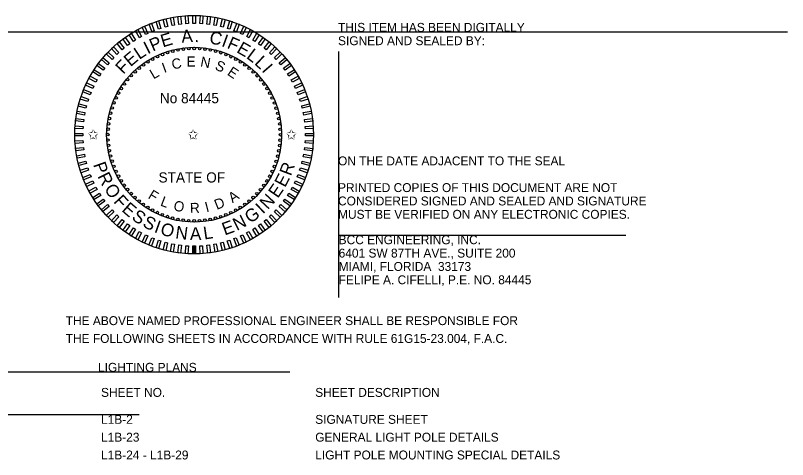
# Model space of a CAD drawing. Extents: x -811.2 to -795, y -2295.2 to -2235.1.
# Drawn here: x -802.94 to -796.87, y -2238.99 to -2235.5 of the extents above; entities that cross this region are included whole.
import ezdxf

# ---------------------------------------------------------------- set-up
doc = ezdxf.new("R2010")
doc.units = 0
for name, color, linetype in [('AdhocPoint_dp', 7, 'Continuous'), ('PlotBorder_dp', 7, 'Continuous'), ('TextMinor', 7, 'Continuous'), ('TextMisc', 7, 'Continuous'), ('TextShtNo', 7, 'Continuous')]:
    doc.layers.add(name, color=color, linetype=linetype)

msp = doc.modelspace()

# ---------------------------------------------------------------- linework, layer by layer
at = {"layer": 'AdhocPoint_dp'}
for p, q in [((-808.3596, -2235.6292), (-796.8708, -2235.6292)), ((-800.3974, -2235.7843), (-800.3974, -2237.719)), ((-800.3974, -2237.229), (-798.1407, -2237.229)), ((-809.3854, -2238.3022), (-800.7818, -2238.3022)), ((-801.9648, -2238.6414), (-810.4432, -2238.6414))]:
    msp.add_line(p, q, dxfattribs=at)
at = {"layer": 'TextMinor'}
for radius in [0.9375, 0.6875]:
    msp.add_circle((-801.5329, -2236.4379), radius, dxfattribs=at)
at = {"layer": 'TextShtNo'}
for p, q in [((-801.5429, -2237.3754), (-801.5431, -2237.3129)), ((-801.5329, -2237.3754), (-801.5331, -2237.3129)), ((-801.5229, -2237.3754), (-801.5231, -2237.3129))]:
    msp.add_line(p, q, dxfattribs=at)
for points in [[(-801.6869, -2235.5764), (-801.7067, -2235.5802), (-801.7184, -2235.5189), (-801.6986, -2235.5151)], [(-801.6325, -2235.5685), (-801.6525, -2235.571), (-801.6603, -2235.5091), (-801.6403, -2235.5065)], [(-801.5777, -2235.5639), (-801.5978, -2235.5652), (-801.6018, -2235.5029), (-801.5816, -2235.5016)], [(-801.5227, -2235.5629), (-801.5429, -2235.5629), (-801.5429, -2235.5004), (-801.5227, -2235.5004)], [(-801.4678, -2235.5652), (-801.488, -2235.564), (-801.484, -2235.5016), (-801.4639, -2235.5029)], [(-801.4131, -2235.571), (-801.4332, -2235.5685), (-801.4254, -2235.5066), (-801.4053, -2235.5091)], [(-801.359, -2235.5803), (-801.3788, -2235.5765), (-801.3671, -2235.5152), (-801.3473, -2235.5189)], [(-801.8456, -2235.6206), (-801.8643, -2235.628), (-801.8873, -2235.5699), (-801.8686, -2235.5625)], [(-801.7936, -2235.6025), (-801.8128, -2235.6088), (-801.8321, -2235.5494), (-801.8129, -2235.5432)], [(-801.7407, -2235.5878), (-801.7602, -2235.5928), (-801.7758, -2235.5324), (-801.7562, -2235.5273)], [(-801.3054, -2235.5929), (-801.325, -2235.5879), (-801.3095, -2235.5274), (-801.2899, -2235.5324)], [(-801.2528, -2235.6088), (-801.272, -2235.6026), (-801.2527, -2235.5432), (-801.2335, -2235.5494)], [(-801.2013, -2235.6281), (-801.2201, -2235.6206), (-801.1971, -2235.5626), (-801.1783, -2235.57)], [(-801.9455, -2235.6662), (-801.9632, -2235.6759), (-801.9933, -2235.6212), (-801.9756, -2235.6115)], [(-801.8963, -2235.6418), (-801.9145, -2235.6504), (-801.9411, -2235.5939), (-801.9229, -2235.5853)], [(-801.1511, -2235.6505), (-801.1694, -2235.6419), (-801.1428, -2235.5854), (-801.1246, -2235.594)], [(-801.1025, -2235.676), (-801.1201, -2235.6663), (-801.0901, -2235.6116), (-801.0724, -2235.6213)], [(-802.039, -2235.724), (-802.0553, -2235.7359), (-802.092, -2235.6853), (-802.0757, -2235.6735)], [(-801.9932, -2235.6936), (-802.0102, -2235.7044), (-802.0437, -2235.6517), (-802.0266, -2235.6409)], [(-801.0555, -2235.7045), (-801.0725, -2235.6937), (-801.039, -2235.641), (-801.022, -2235.6518)], [(-801.0104, -2235.736), (-801.0267, -2235.7241), (-800.99, -2235.6736), (-800.9737, -2235.6854)], [(-802.1245, -2235.793), (-802.1392, -2235.8069), (-802.182, -2235.7613), (-802.1672, -2235.7475)], [(-802.0828, -2235.7572), (-802.0984, -2235.77), (-802.1382, -2235.7219), (-802.1226, -2235.7091)], [(-800.9673, -2235.7702), (-800.9829, -2235.7573), (-800.9431, -2235.7092), (-800.9275, -2235.722)], [(-800.9265, -2235.807), (-800.9412, -2235.7932), (-800.8985, -2235.7477), (-800.8838, -2235.7615)], [(-802.1638, -2235.8315), (-802.1776, -2235.8462), (-802.2232, -2235.8034), (-802.2093, -2235.7887)], [(-800.8881, -2235.8463), (-800.9019, -2235.8316), (-800.8564, -2235.7889), (-800.8426, -2235.8036)], [(-802.2349, -2235.9153), (-802.2467, -2235.9316), (-802.2972, -2235.8949), (-802.2854, -2235.8786)], [(-802.2007, -2235.8723), (-802.2135, -2235.8878), (-802.2616, -2235.848), (-802.2488, -2235.8325)], [(-800.8522, -2235.888), (-800.8651, -2235.8724), (-800.817, -2235.8326), (-800.8041, -2235.8482)], [(-800.819, -2235.9318), (-800.8309, -2235.9155), (-800.7804, -2235.8788), (-800.7685, -2235.8951)], [(-802.2663, -2235.9604), (-802.2771, -2235.9775), (-802.3298, -2235.944), (-802.319, -2235.927)], [(-800.7887, -2235.9776), (-800.7995, -2235.9606), (-800.7468, -2235.9271), (-800.7359, -2235.9442)], [(-802.2948, -2236.0074), (-802.3045, -2236.0251), (-802.3593, -2235.995), (-802.3495, -2235.9773)], [(-800.7612, -2236.0253), (-800.7709, -2236.0076), (-800.7162, -2235.9775), (-800.7065, -2235.9952)], [(-802.3203, -2236.0561), (-802.3289, -2236.0744), (-802.3854, -2236.0478), (-802.3768, -2236.0295)], [(-800.7368, -2236.0745), (-800.7454, -2236.0563), (-800.6889, -2236.0297), (-800.6803, -2236.048)], [(-802.3428, -2236.1063), (-802.3502, -2236.1251), (-802.4082, -2236.1021), (-802.4008, -2236.0833)], [(-800.7156, -2236.1252), (-800.723, -2236.1065), (-800.665, -2236.0835), (-800.6575, -2236.1023)], [(-802.362, -2236.1578), (-802.3682, -2236.177), (-802.4276, -2236.1577), (-802.4214, -2236.1385)], [(-800.6976, -2236.1772), (-800.7038, -2236.158), (-800.6444, -2236.1387), (-800.6382, -2236.1579)], [(-802.3779, -2236.2104), (-802.383, -2236.23), (-802.4434, -2236.2144), (-802.4384, -2236.1949)], [(-800.6829, -2236.2301), (-800.6879, -2236.2106), (-800.6274, -2236.1951), (-800.6224, -2236.2146)], [(-802.3905, -2236.2639), (-802.3943, -2236.2837), (-802.4557, -2236.272), (-802.4519, -2236.2522)], [(-800.6715, -2236.2839), (-800.6753, -2236.2641), (-800.6139, -2236.2524), (-800.6102, -2236.2722)], [(-802.3998, -2236.3181), (-802.4023, -2236.3381), (-802.4643, -2236.3303), (-802.4617, -2236.3103)], [(-800.6635, -2236.3383), (-800.666, -2236.3183), (-800.6041, -2236.3105), (-800.6016, -2236.3305)], [(-802.4056, -2236.3728), (-802.4069, -2236.3929), (-802.4692, -2236.389), (-802.4679, -2236.3689)], [(-800.659, -2236.3931), (-800.6603, -2236.373), (-800.5979, -2236.369), (-800.5967, -2236.3892)], [(-802.408, -2236.4277), (-802.408, -2236.4479), (-802.4704, -2236.4479), (-802.4704, -2236.4277)], [(-802.4069, -2236.4827), (-802.4056, -2236.5028), (-802.4679, -2236.5067), (-802.4692, -2236.4866)], [(-800.6603, -2236.503), (-800.659, -2236.4829), (-800.5967, -2236.4868), (-800.5979, -2236.5069)], [(-800.6579, -2236.4481), (-800.6579, -2236.4279), (-800.5955, -2236.4279), (-800.5955, -2236.4481)], [(-802.4023, -2236.5375), (-802.3998, -2236.5575), (-802.4618, -2236.5653), (-802.4643, -2236.5453)], [(-800.6661, -2236.5577), (-800.6635, -2236.5376), (-800.6016, -2236.5455), (-800.6041, -2236.5655)], [(-802.3944, -2236.5918), (-802.3906, -2236.6117), (-802.4519, -2236.6234), (-802.4557, -2236.6035)], [(-800.6753, -2236.6119), (-800.6715, -2236.592), (-800.6102, -2236.6037), (-800.614, -2236.6236)], [(-802.383, -2236.6456), (-802.378, -2236.6652), (-802.4385, -2236.6807), (-802.4435, -2236.6612)], [(-800.6879, -2236.6654), (-800.6829, -2236.6458), (-800.6224, -2236.6613), (-800.6274, -2236.6809)], [(-802.3683, -2236.6986), (-802.362, -2236.7178), (-802.4214, -2236.7371), (-802.4277, -2236.7179)], [(-800.7039, -2236.718), (-800.6976, -2236.6988), (-800.6382, -2236.7181), (-800.6445, -2236.7373)], [(-802.3503, -2236.7505), (-802.3428, -2236.7693), (-802.4009, -2236.7923), (-802.4083, -2236.7735)], [(-800.7231, -2236.7695), (-800.7157, -2236.7507), (-800.6576, -2236.7737), (-800.665, -2236.7925)], [(-802.329, -2236.8012), (-802.3204, -2236.8195), (-802.3769, -2236.8461), (-802.3855, -2236.8278)], [(-802.3046, -2236.8505), (-802.2949, -2236.8682), (-802.3496, -2236.8983), (-802.3593, -2236.8806)], [(-800.7455, -2236.8197), (-800.7369, -2236.8014), (-800.6804, -2236.828), (-800.689, -2236.8463)], [(-802.2772, -2236.8982), (-802.2664, -2236.9152), (-802.3191, -2236.9487), (-802.3299, -2236.9316)], [(-800.7996, -2236.9154), (-800.7888, -2236.8983), (-800.736, -2236.9318), (-800.7469, -2236.9488)], [(-800.771, -2236.8684), (-800.7613, -2236.8507), (-800.7066, -2236.8808), (-800.7163, -2236.8984)], [(-802.2468, -2236.944), (-802.235, -2236.9603), (-802.2855, -2236.997), (-802.2973, -2236.9807)], [(-800.831, -2236.9605), (-800.8191, -2236.9441), (-800.7686, -2236.9808), (-800.7805, -2236.9972)], [(-802.2136, -2236.9878), (-802.2008, -2237.0034), (-802.2489, -2237.0432), (-802.2618, -2237.0276)], [(-802.1778, -2237.0295), (-802.1639, -2237.0442), (-802.2095, -2237.0869), (-802.2233, -2237.0722)], [(-800.902, -2237.0443), (-800.8882, -2237.0296), (-800.8427, -2237.0723), (-800.8565, -2237.0871)], [(-800.8652, -2237.0035), (-800.8523, -2236.9879), (-800.8042, -2237.0278), (-800.8171, -2237.0433)], [(-802.1394, -2237.0688), (-802.1246, -2237.0826), (-802.1674, -2237.1281), (-802.1821, -2237.1143)], [(-800.9414, -2237.0827), (-800.9266, -2237.0689), (-800.8839, -2237.1144), (-800.8986, -2237.1282)], [(-802.0985, -2237.1056), (-802.083, -2237.1185), (-802.1228, -2237.1666), (-802.1383, -2237.1537)], [(-802.0555, -2237.1398), (-802.0392, -2237.1517), (-802.0759, -2237.2022), (-802.0922, -2237.1903)], [(-801.0268, -2237.1518), (-801.0105, -2237.1399), (-800.9738, -2237.1904), (-800.9901, -2237.2023)], [(-800.983, -2237.1186), (-800.9675, -2237.1057), (-800.9277, -2237.1538), (-800.9432, -2237.1667)], [(-802.0104, -2237.1712), (-801.9933, -2237.1821), (-802.0268, -2237.2348), (-802.0438, -2237.224)], [(-801.9634, -2237.1998), (-801.9457, -2237.2095), (-801.9758, -2237.2642), (-801.9935, -2237.2545)], [(-801.1203, -2237.2096), (-801.1026, -2237.1999), (-801.0725, -2237.2546), (-801.0902, -2237.2643)], [(-801.0727, -2237.1822), (-801.0556, -2237.1713), (-801.0222, -2237.2241), (-801.0392, -2237.2349)], [(-801.9147, -2237.2253), (-801.8964, -2237.2339), (-801.923, -2237.2904), (-801.9413, -2237.2818)], [(-801.8645, -2237.2477), (-801.8457, -2237.2552), (-801.8687, -2237.3132), (-801.8875, -2237.3058)], [(-801.813, -2237.2669), (-801.7938, -2237.2732), (-801.8131, -2237.3326), (-801.8323, -2237.3263)], [(-801.2722, -2237.2732), (-801.253, -2237.267), (-801.2337, -2237.3264), (-801.2529, -2237.3326)], [(-801.2203, -2237.2552), (-801.2015, -2237.2478), (-801.1785, -2237.3058), (-801.1973, -2237.3133)], [(-801.1696, -2237.234), (-801.1513, -2237.2254), (-801.1247, -2237.2819), (-801.143, -2237.2905)], [(-801.7604, -2237.2829), (-801.7409, -2237.2879), (-801.7564, -2237.3484), (-801.7759, -2237.3434)], [(-801.7069, -2237.2955), (-801.6871, -2237.2993), (-801.6988, -2237.3606), (-801.7186, -2237.3568)], [(-801.6527, -2237.3047), (-801.6327, -2237.3073), (-801.6405, -2237.3692), (-801.6605, -2237.3667)], [(-801.598, -2237.3106), (-801.5779, -2237.3118), (-801.5818, -2237.3741), (-801.602, -2237.3729)], [(-801.5431, -2237.3129), (-801.5229, -2237.3129), (-801.5229, -2237.3754), (-801.5431, -2237.3754)], [(-801.4881, -2237.3118), (-801.468, -2237.3106), (-801.4641, -2237.3729), (-801.4842, -2237.3741)], [(-801.4334, -2237.3073), (-801.4133, -2237.3048), (-801.4055, -2237.3667), (-801.4255, -2237.3692)], [(-801.379, -2237.2993), (-801.3591, -2237.2955), (-801.3474, -2237.3569), (-801.3673, -2237.3607)], [(-801.3252, -2237.288), (-801.3056, -2237.2829), (-801.2901, -2237.3434), (-801.3097, -2237.3484)]]:
    msp.add_lwpolyline(points, close=True, dxfattribs=at)
for centre in [(-801.6173, -2235.7657), (-801.5749, -2235.7617), (-801.5324, -2235.7604), (-801.4898, -2235.7618), (-801.4475, -2235.7658), (-801.8209, -2235.8247), (-801.7818, -2235.8078), (-801.7417, -2235.7934), (-801.7009, -2235.7816), (-801.6593, -2235.7723), (-801.4054, -2235.7725), (-801.3639, -2235.7818), (-801.323, -2235.7938), (-801.283, -2235.8082), (-801.244, -2235.8251), (-801.9307, -2235.8895), (-801.8955, -2235.8656), (-801.8588, -2235.8439), (-801.2061, -2235.8445), (-801.1694, -2235.8662), (-801.9963, -2235.9436), (-801.9643, -2235.9155), (-801.1343, -2235.8901), (-801.1007, -2235.9163), (-801.0688, -2235.9444), (-802.0546, -2236.0056), (-802.0264, -2235.9737), (-801.0387, -2235.9745), (-801.0106, -2236.0065), (-802.0807, -2236.0392), (-800.9845, -2236.0401), (-802.1263, -2236.111), (-802.1046, -2236.0744), (-800.9606, -2236.0754), (-800.939, -2236.112), (-802.1626, -2236.188), (-802.1457, -2236.1489), (-800.9197, -2236.1499), (-800.9028, -2236.189), (-802.1771, -2236.228), (-800.8884, -2236.2291), (-802.1983, -2236.3104), (-802.189, -2236.2689), (-800.8766, -2236.27), (-800.8674, -2236.3115), (-802.205, -2236.3524), (-800.8607, -2236.3535), (-802.209, -2236.3948), (-800.8568, -2236.3959), (-802.2104, -2236.4373), (-802.2091, -2236.4799), (-800.8568, -2236.481), (-800.8555, -2236.4385), (-802.2051, -2236.5222), (-800.8609, -2236.5234), (-802.1985, -2236.5643), (-802.1893, -2236.6058), (-800.8769, -2236.6069), (-800.8676, -2236.5654), (-802.1774, -2236.6467), (-800.8888, -2236.6478), (-802.163, -2236.6868), (-802.1462, -2236.7258), (-800.9202, -2236.7269), (-800.9032, -2236.6878), (-802.1269, -2236.7638), (-800.9395, -2236.7648), (-802.1052, -2236.8004), (-802.0813, -2236.8356), (-800.9852, -2236.8366), (-800.9612, -2236.8014), (-802.0553, -2236.8693), (-802.0272, -2236.9012), (-801.0395, -2236.9021), (-801.0113, -2236.8702), (-801.9971, -2236.9314), (-801.9652, -2236.9595), (-801.1015, -2236.9602), (-801.0696, -2236.9321), (-801.9316, -2236.9856), (-801.8964, -2237.0096), (-801.8598, -2237.0313), (-801.207, -2237.0318), (-801.1704, -2237.0102), (-801.1352, -2236.9863), (-801.8219, -2237.0506), (-801.7828, -2237.0676), (-801.7428, -2237.082), (-801.702, -2237.0939), (-801.365, -2237.0942), (-801.3241, -2237.0824), (-801.2841, -2237.068), (-801.245, -2237.0511), (-801.6604, -2237.1033), (-801.6184, -2237.1099), (-801.576, -2237.114), (-801.5329, -2237.1154), (-801.4909, -2237.1141), (-801.4486, -2237.1101), (-801.4065, -2237.1035)]:
    msp.add_circle(centre, 0.01, dxfattribs=at)

# ---------------------------------------------------------------- texts
at = {"layer": 'PlotBorder_dp'}
for s, p in [('THIS ITEM HAS BEEN DIGITALLY', (-800.4024, -2235.6292)), ('SIGNED AND SEALED BY:', (-800.4024, -2235.7342)), ('ON THE DATE ADJACENT TO THE SEAL', (-800.4024, -2236.6792)), ('PRINTED COPIES OF THIS DOCUMENT ARE NOT ', (-800.4024, -2236.8892)), ('CONSIDERED SIGNED AND SEALED AND SIGNATURE ', (-800.4024, -2236.9942)), ('MUST BE VERIFIED ON ANY ELECTRONIC COPIES.', (-800.4024, -2237.0992)), ('BCC ENGINEERING, INC.', (-800.3974, -2237.299)), ('6401 SW 87TH AVE., SUITE 200', (-800.3974, -2237.404)), ('MIAMI, FLORIDA  33173', (-800.3974, -2237.509)), ('FELIPE A. CIFELLI, P.E. NO. 84445', (-800.3974, -2237.614)), ('THE ABOVE NAMED PROFESSIONAL ENGINEER SHALL BE RESPONSIBLE FOR ', (-802.5415, -2237.9352)), ('THE FOLLOWING SHEETS IN ACCORDANCE WITH RULE 61G15-23.004, F.A.C.', (-802.5415, -2238.0752)), ('LIGHTING PLANS', (-802.2878, -2238.3022))]:
    msp.add_text(s, height=0.07, dxfattribs=at).set_placement(p)
at = {"layer": 'TextMisc'}
for s, p in [('SHEET NO.', (-802.2643, -2238.4992)), ('SHEET DESCRIPTION', (-800.5815, -2238.4992)), ('L1B-2', (-802.2643, -2238.7114)), ('SIGNATURE SHEET', (-800.5815, -2238.7114)), ('L1B-23', (-802.2643, -2238.8514)), ('GENERAL LIGHT POLE DETAILS', (-800.5815, -2238.8514)), ('L1B-24 - L1B-29', (-802.2643, -2238.9914)), ('LIGHT POLE MOUNTING SPECIAL DETAILS', (-800.5815, -2238.9914))]:
    msp.add_text(s, height=0.07, dxfattribs=at).set_placement(p)
at = {"layer": 'TextShtNo'}
for s, height, rotation, p in [('E', 0.1, 16.54261, (-801.7793, -2235.7522)), ('A', 0.1, 4.42103, (-801.6298, -2235.7157)), ('C', 0.1, 347.7999, (-801.4192, -2235.7182)), ('P', 0.1, 23.28287, (-801.8581, -2235.7858)), ('.', 0.1, 356.65403, (-801.5313, -2235.7092)), ('I', 0.1, 340.0631, (-801.3234, -2235.74)), ('F', 0.1, 336.52991, (-801.2807, -2235.7543)), ('L', 0.1, 33.07918, (-801.9643, -2235.8507)), ('I', 0.1, 26.81606, (-801.8977, -2235.8071)), ('E', 0.1, 330.07956, (-801.2055, -2235.7869)), ('L', 0.1, 323.03732, (-801.1282, -2235.832)), ('E', 0.1, 40.12142, (-802.033, -2235.908)), ('L', 0.1, 316.7742, (-801.0645, -2235.8797)), ('F', 0.1, 46.57177, (-802.0894, -2235.9675)), ('I', 0.08, 20.01168, (-801.7686, -2235.9538)), ('C', 0.08, 12.20255, (-801.7007, -2235.9263)), ('E', 0.08, 0.41861, (-801.5926, -2235.9028)), ('N', 0.08, 349.29143, (-801.4883, -2235.9013)), ('S', 0.08, 337.02207, (-801.3753, -2235.9231)), ('I', 0.1, 310.51108, (-801.0064, -2235.9342)), ('L', 0.08, 30.40215, (-801.8521, -2236.0043)), ('E', 0.08, 325.86633, (-801.2786, -2235.9633)), ('P', 0.1, 289.40551, (-802.3276, -2236.6725)), ('R', 0.1, 69.5134, (-800.7727, -2236.7676)), ('R', 0.1, 296.14576, (-802.2946, -2236.7641)), ('E', 0.1, 62.47116, (-800.8189, -2236.8583)), ('O', 0.1, 303.96711, (-802.2431, -2236.8647)), ('E', 0.1, 55.42892, (-800.8758, -2236.9427)), ('F', 0.1, 312.62798, (-802.1708, -2236.9668)), ('F', 0.08, 328.72408, (-801.901, -2236.9345)), ('A', 0.08, 34.49917, (-801.2311, -2236.9773)), ('N', 0.1, 47.17876, (-800.9551, -2237.0317)), ('E', 0.1, 319.07833, (-802.1073, -2237.0351)), ('L', 0.08, 339.29159, (-801.8037, -2236.9936)), ('O', 0.08, 349.68206, (-801.699, -2237.0333)), ('I', 0.08, 14.20366, (-801.4369, -2237.0485)), ('D', 0.08, 22.01279, (-801.3549, -2237.0298)), ('R', 0.08, 2.33977, (-801.5645, -2237.0552)), ('G', 0.1, 35.11153, (-801.092, -2237.1394)), ('I', 0.1, 43.64556, (-800.9928, -2237.0662)), ('S', 0.1, 326.12056, (-802.0297, -2237.101)), ('S', 0.1, 333.193, (-801.9443, -2237.1572)), ('N', 0.1, 26.86136, (-801.1972, -2237.1954)), ('I', 0.1, 340.26543, (-801.8526, -2237.2023)), ('O', 0.1, 343.79863, (-801.8049, -2237.2206)), ('E', 0.1, 19.81912, (-801.2926, -2237.2309)), ('N', 0.1, 352.45949, (-801.6839, -2237.2526)), ('A', 0.1, 0.70966, (-801.5655, -2237.2659)), ('L', 0.1, 8.47665, (-801.4533, -2237.2627))]:
    msp.add_text(s, height=height, rotation=rotation, dxfattribs=at).set_placement(p)
for s, p in [('No 84445', (-801.8019, -2236.1907)), ('✩', (-802.3679, -2236.4758)), ('✩', (-801.5832, -2236.4758)), ('✩', (-800.8113, -2236.4758)), ('STATE OF', (-801.8126, -2236.8141))]:
    msp.add_text(s, height=0.08, dxfattribs=at).set_placement(p)

doc.saveas('drawing.dxf')
